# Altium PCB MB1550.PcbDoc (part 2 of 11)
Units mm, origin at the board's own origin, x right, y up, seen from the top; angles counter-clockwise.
Board outline 154.81 x 170.69 mm, 6 copper layers (Top Layer, Signal Layer 1, Signal Layer 2, Signal Layer 3, Signal Layer 4, Bottom Layer), stack 1.49 mm thick; 810 components, 633 nets, 2973 pads, 2150 vias.
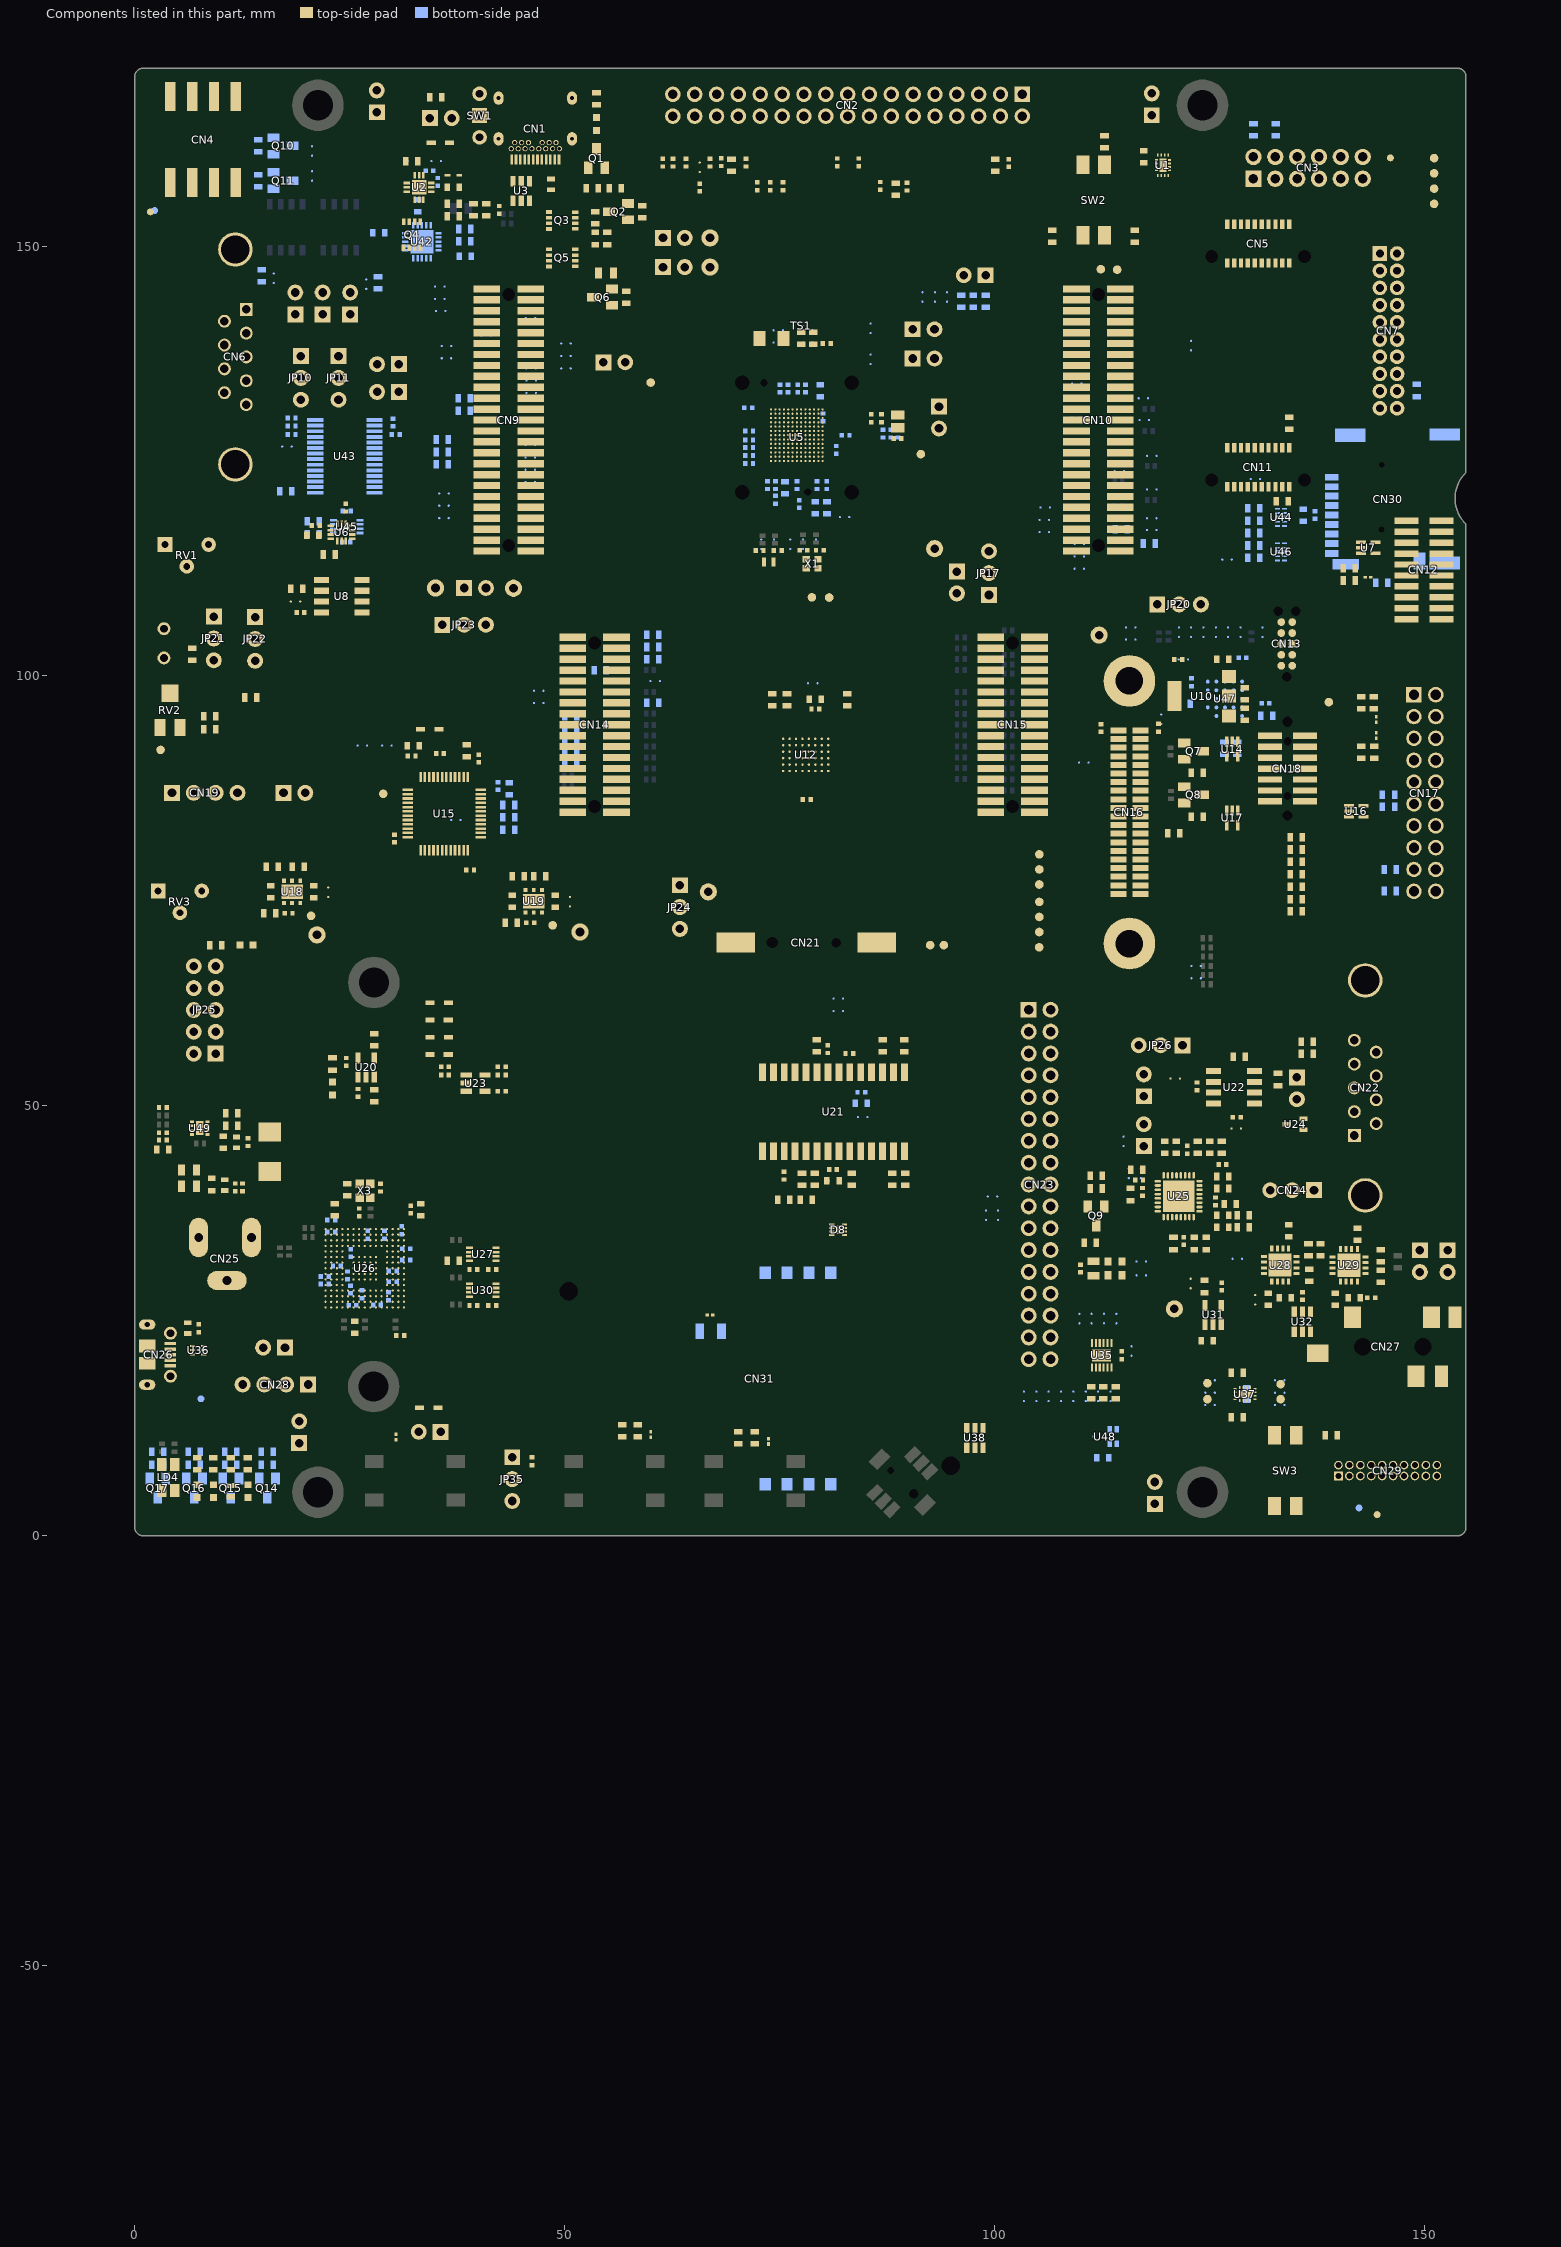
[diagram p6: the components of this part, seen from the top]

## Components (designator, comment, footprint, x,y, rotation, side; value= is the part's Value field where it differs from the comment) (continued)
R251 "Resistor" R0603 11.264,49.162 r180 top value=1K
R252 "Resistor" R0805 6.309,40.655 r180 top value=0R
RV1 "" POT_BOURNS_3386P-1-101TLF 6.055,115.265 r0 top value=10K
RV2 "" POT_BOURNS_3314J-1 4.1,96 r0 top value=10K
RV3 "" POT_BOURNS_3386P 5.254,74.98 r0 top value=50K
SB1 "" SOLDER-BRIDGE_R0603-0R 65.7,159.2 r270 top
SB2 "" SOLDER-BRIDGE_R0603-0R 18.75,108.65 r180 top
SB3 "" SOLDER-BRIDGE_R0603-0R 22.5,74.9 r270 top
SB4 "" SOLDER-BRIDGE_R0603-0R 50.6,73.8 r270 top
SB5 "" SOLDER-BRIDGE_R0603-0R 120.95,53.175 r0 top
SB6 "" SOLDER-BRIDGE_R0603-0R 128.05,47.375 r0 top
SB7 "" SOLDER-BRIDGE_R0603-0R 122.8,29.3 r90 top
SB8 "" SOLDER-BRIDGE_R0603-0R 130.3,27.4 r90 top
SB9 "" SOLDER-BRIDGE_R0603-0R 20.625,161.1 r270 bottom
SB10 "" SOLDER-BRIDGE_R0603-0R 32.225,159.875 r0 bottom
SB11 "" SOLDER-BRIDGE_R0603-0R 35.1,159.875 r180 bottom
SB12 "" SOLDER-BRIDGE_R0603-0R 20.625,158.2 r270 bottom
SB13 "" SOLDER-BRIDGE_R0603-0R 16.175,146.3 r270 bottom
SB14 "" SOLDER-BRIDGE_R0603-0R 26.925,145.525 r90 bottom
SB15 "" SOLDER-BRIDGE_R0603-0R 35.525,145.275 r180 bottom
SB16 "" SOLDER-BRIDGE_R0603-0R 94.475,144.025 r90 bottom
SB17 "" SOLDER-BRIDGE_R0603-0R 93.05,144.025 r90 bottom
SB18 "" SOLDER-BRIDGE_R0603-0R 91.6,144.025 r90 bottom
SB19 "" SOLDER-BRIDGE_R0603-0R 35.525,143.85 r180 bottom
SB20 "" SOLDER-BRIDGE_R0603-0R 35.525,142.45 r0 bottom
SB21 "" SOLDER-BRIDGE_R0603-0R 46.075,141.625 r180 bottom
SB22 "" SOLDER-BRIDGE_R0603-0R 40.9,141.4 r180 bottom
SB23 "" SOLDER-BRIDGE_R0603-0R 85.575,140.375 r90 bottom
SB24 "" SOLDER-BRIDGE_R0603-0R 78.225,140.2 r0 bottom
SB25 "" SOLDER-BRIDGE_R0603-0R 74.9,140.2 r180 bottom
SB26 "" SOLDER-BRIDGE_R0603-0R 46.05,140.075 r180 bottom
SB27 "" SOLDER-BRIDGE_R0603-0R 40.9,139.575 r180 bottom
SB28 "" SOLDER-BRIDGE_R0603-0R 122.85,138.475 r270 bottom
SB29 "" SOLDER-BRIDGE_R0603-0R 78.225,138.775 r0 bottom
SB30 "" SOLDER-BRIDGE_R0603-0R 74.9,138.775 r180 bottom
SB31 "" SOLDER-BRIDGE_R0603-0R 50.1,138.675 r0 bottom
SB32 "" SOLDER-BRIDGE_R0603-0R 46.05,138.65 r0 bottom
SB33 "" SOLDER-BRIDGE_R0603-0R 36.3,138.375 r180 bottom
SB34 "" SOLDER-BRIDGE_R0603-0R 85.575,136.875 r270 bottom
SB35 "" SOLDER-BRIDGE_R0603-0R 40.9,137.4 r180 bottom
SB36 "" SOLDER-BRIDGE_R0603-0R 50.1,137.225 r0 bottom
SB37 "" SOLDER-BRIDGE_R0603-0R 46.05,137.2 r0 bottom
SB38 "" SOLDER-BRIDGE_R0603-0R 36.3,136.95 r180 bottom
SB39 "" SOLDER-BRIDGE_R0603-0R 50.1,135.775 r0 bottom
SB40 "" SOLDER-BRIDGE_R0603-0R 46.05,135.775 r0 bottom
SB41 "" SOLDER-BRIDGE_R0603-0R 46.05,134.35 r0 bottom
SB42 "" SOLDER-BRIDGE_R0603-0R 109.5,134 r0 bottom
SB43 "" SOLDER-BRIDGE_R0603-0R 46.05,132.925 r0 bottom
SB44 "" SOLDER-BRIDGE_R0603-0R 109.5,132.575 r0 bottom
SB45 "" SOLDER-BRIDGE_R0603-0R 117.35,132.3 r180 bottom
SB46 "" SOLDER-BRIDGE_R0603-0R 41.025,132.3 r0 bottom
SB47 "" SOLDER-BRIDGE_R0603-0R 109.5,131.15 r0 bottom
SB48 "" SOLDER-BRIDGE_R0603-0R 114.425,131.05 r0 bottom
SB49 "" SOLDER-BRIDGE_R0603-0R 41.033,130.85 r0 bottom
SB50 "" SOLDER-BRIDGE_R0603-0R 117.35,129.75 r0 bottom
SB51 "" SOLDER-BRIDGE_R0603-0R 109.5,128.725 r0 bottom
SB52 "" SOLDER-BRIDGE_R0603-0R 41.025,128.5 r0 bottom
SB53 "" SOLDER-BRIDGE_R0603-0R 109.5,127.4 r0 bottom
SB54 "" SOLDER-BRIDGE_R0603-0R 114.425,127.175 r180 bottom
SB55 "" SOLDER-BRIDGE_R0603-0R 46.05,126.875 r180 bottom
SB56 "" SOLDER-BRIDGE_R0603-0R 17.65,126.675 r0 bottom
SB57 "" SOLDER-BRIDGE_R0603-0R 118.225,125.6 r0 bottom
SB58 "" SOLDER-BRIDGE_R0603-0R 46.05,125.4 r180 bottom
SB59 "" SOLDER-BRIDGE_R0603-0R 40.917,124.864 r180 bottom
SB60 "" SOLDER-BRIDGE_R0603-0R 46.05,123.975 r180 bottom
SB61 "" SOLDER-BRIDGE_R0603-0R 114.45,123.825 r0 bottom
SB62 "" SOLDER-BRIDGE_R0603-0R 40.917,123.414 r180 bottom
SB63 "" SOLDER-BRIDGE_R0603-0R 109.8,123.4 r0 bottom
SB64 "SB_ON" SOLDER-BRIDGE_R0603-0R 130.375,122.9 r180 bottom
SB65 "" SOLDER-BRIDGE_R0603-0R 46.05,122.55 r180 bottom
SB66 "" SOLDER-BRIDGE_R0603-0R 118.225,121.7 r0 bottom
SB67 "" SOLDER-BRIDGE_R0603-0R 36.012,121.225 r180 bottom
SB68 "" SOLDER-BRIDGE_R0603-0R 46.05,121.1 r180 bottom
SB69 "" SOLDER-BRIDGE_R0603-0R 114.417,120.966 r0 bottom
SB70 "" SOLDER-BRIDGE_R0603-0R 40.9,120.875 r180 bottom
SB71 "" SOLDER-BRIDGE_R0603-0R 36.012,119.8 r180 bottom
SB72 "" SOLDER-BRIDGE_R0603-0R 46.05,119.675 r180 bottom
SB73 "" SOLDER-BRIDGE_R0603-0R 109.8,119.625 r0 bottom
SB74 "" SOLDER-BRIDGE_R0603-0R 105.825,119.6 r0 bottom
SB75 "" SOLDER-BRIDGE_R0603-0R 40.905,118.5 r0 bottom
SB76 "" SOLDER-BRIDGE_R0603-0R 82.6,118.475 r180 bottom
SB77 "" SOLDER-BRIDGE_R0603-0R 118.225,118.35 r0 bottom
SB78 "" SOLDER-BRIDGE_R0603-0R 36.012,118.35 r180 bottom
SB79 "" SOLDER-BRIDGE_R0603-0R 46.05,118.25 r180 bottom
SB80 "" SOLDER-BRIDGE_R0603-0R 109.8,118.2 r0 bottom
SB81 "" SOLDER-BRIDGE_R0603-0R 105.825,118.15 r180 bottom
SB82 "" SOLDER-BRIDGE_R0603-0R 40.905,117.075 r0 bottom
SB83 "" SOLDER-BRIDGE_R0603-0R 118.225,116.975 r0 bottom
SB84 "" SOLDER-BRIDGE_R0603-0R 109.8,116.75 r0 bottom
SB85 "" SOLDER-BRIDGE_R0603-0R 105.825,116.725 r180 bottom
SB86 "" SOLDER-BRIDGE_R0603-0R 74.35,115.275 r90 bottom
SB87 "" SOLDER-BRIDGE_R0603-0R 72.85,115.275 r90 bottom
SB88 "" SOLDER-BRIDGE_R0603-0R 79.225,115.275 r90 bottom
SB89 "" SOLDER-BRIDGE_R0603-0R 77.725,115.275 r90 bottom
SB90 "" SOLDER-BRIDGE_R0603-0R 76.225,115.275 r90 bottom
SB91 "" SOLDER-BRIDGE_R0603-0R 109.8,115.35 r0 bottom
SB92 "" SOLDER-BRIDGE_R0603-0R 109.8,113.9 r0 bottom
SB93 "" SOLDER-BRIDGE_R0603-0R 126.975,113.525 r0 bottom
SB94 "" SOLDER-BRIDGE_R0603-0R 109.8,112.475 r0 bottom
SB95 "" SOLDER-BRIDGE_R0603-0R 131.15,105.15 r270 bottom
SB96 "" SOLDER-BRIDGE_R0603-0R 128.6,105.15 r270 bottom
SB97 "" SOLDER-BRIDGE_R0603-0R 127.15,105.15 r270 bottom
SB98 "" SOLDER-BRIDGE_R0603-0R 125.725,105.15 r270 bottom
SB99 "" SOLDER-BRIDGE_R0603-0R 124.275,105.15 r270 bottom
SB100 "" SOLDER-BRIDGE_R0603-0R 122.85,105.15 r270 bottom
SB101 "" SOLDER-BRIDGE_R0603-0R 121.425,105.15 r270 bottom
SB102 "" SOLDER-BRIDGE_R0603-0R 115.775,105.65 r0 bottom
SB103 "" SOLDER-BRIDGE_R0603-0R 115.775,104.225 r0 bottom
SB104 "" SOLDER-BRIDGE_R0603-0R 121.9,101.925 r0 bottom
SB105 "" SOLDER-BRIDGE_R0603-0R 60.475,99.4 r0 bottom
SB106 "" SOLDER-BRIDGE_R0603-0R 78.9,99.15 r180 bottom
SB107 "" SOLDER-BRIDGE_R0603-0R 47.025,98.275 r180 bottom
SB108 "" SOLDER-BRIDGE_R0603-0R 47.025,96.85 r180 bottom
SB109 "" SOLDER-BRIDGE_R0603-0R 119.384,94.921 r90 bottom
SB110 "" SOLDER-BRIDGE_R0603-0R 29.275,91.9 r0 bottom
SB111 "" SOLDER-BRIDGE_R0603-0R 26.425,91.9 r0 bottom
SB112 "" SOLDER-BRIDGE_R0603-0R 110.425,89.925 r180 bottom
SB113 "" SOLDER-BRIDGE_R0603-0R 37.4,83.25 r180 bottom
SB114 "" SOLDER-BRIDGE_R0603-0R 123.375,66.275 r0 bottom
SB115 "" SOLDER-BRIDGE_R0603-0R 123.375,64.85 r0 bottom
SB116 "" SOLDER-BRIDGE_R0603-0R 81.775,62.475 r0 bottom
SB117 "" SOLDER-BRIDGE_R0603-0R 81.775,61.025 r0 bottom
SB118 "" SOLDER-BRIDGE_R0603-0R 84.7,48.7 r180 bottom
SB119 "" SOLDER-BRIDGE_R0603-0R 115,45.825 r90 bottom
SB120 "" SOLDER-BRIDGE_R0603-0R 117,42.2 r270 bottom
SB121 "" SOLDER-BRIDGE_R0603-0R 115.6,42.2 r270 bottom
SB122 "" SOLDER-BRIDGE_R0603-0R 81.3,41.3 r180 bottom
SB123 "" SOLDER-BRIDGE_R0603-0R 99.7,39.475 r0 bottom
SB124 "" SOLDER-BRIDGE_R0603-0R 100.4,37.35 r270 bottom
SB125 "" SOLDER-BRIDGE_R0603-0R 99,37.35 r270 bottom
SB126 "" SOLDER-BRIDGE_R0603-0R 128.275,32.225 r180 bottom
SB127 "" SOLDER-BRIDGE_R0603-0R 117.1,31.9 r180 bottom
SB128 "" SOLDER-BRIDGE_R0603-0R 117.1,30.3 r180 bottom
SB129 "" SOLDER-BRIDGE_R0603-0R 114.15,25.225 r90 bottom
SB130 "" SOLDER-BRIDGE_R0603-0R 112.725,25.225 r90 bottom
SB131 "" SOLDER-BRIDGE_R0603-0R 111.275,25.225 r90 bottom
SB132 "" SOLDER-BRIDGE_R0603-0R 109.85,25.225 r90 bottom
SB133 "" SOLDER-BRIDGE_R0603-0R 115.925,21.55 r270 bottom
SB134 "" SOLDER-BRIDGE_R0603-0R 133.1,18.1 r0 bottom
SB135 "" SOLDER-BRIDGE_R0603-0R 125.1,18.1 r180 bottom
SB136 "" SOLDER-BRIDGE_R0603-0R 113.475,16.275 r270 bottom
SB137 "" SOLDER-BRIDGE_R0603-0R 112.025,16.275 r270 bottom
SB138 "" SOLDER-BRIDGE_R0603-0R 110.6,16.275 r270 bottom
SB139 "" SOLDER-BRIDGE_R0603-0R 109.15,16.275 r270 bottom
SB140 "" SOLDER-BRIDGE_R0603-0R 107.725,16.275 r270 bottom
SB141 "" SOLDER-BRIDGE_R0603-0R 106.275,16.275 r270 bottom
SB142 "" SOLDER-BRIDGE_R0603-0R 104.85,16.275 r270 bottom
SB143 "" SOLDER-BRIDGE_R0603-0R 103.4,16.275 r270 bottom
SB144 "" SOLDER-BRIDGE_R0603-0R 133.1,16.65 r0 bottom
SB145 "" SOLDER-BRIDGE_R0603-0R 125.1,16.65 r180 bottom
SB146 "" SOLDER-BRIDGE_R0603-0R 133.1,15.225 r0 bottom
SB147 "" SOLDER-BRIDGE_R0603-0R 125.1,15.225 r180 bottom
SW1 "SW_MECA_1K2" SWI_EAO_09-03290-01_EXTENDED_STRAIGHT_BLACK 40.1,165.175 r0 top value="Mechanical Slide Switch 1K2"
SW2 "SWITCH_2WAY" SWI_C&K_SDA02H1SBD_2POS 111.525,155.35 r0 top
SW3 "SWITCH_2WAY" SWI_C&K_SDA02H1SBD_2POS 133.8,7.6 r0 top
TP1 "Test Point" TP_SMD_1MM 151.1,160.225 r270 top
TP2 "Test Point" TP_SMD_1MM 151.1,158.45 r90 top
TP3 "Test Point" TP_SMD_1MM 151.1,156.675 r90 top
TP4 "Test Point" TP_SMD_1MM 151.1,154.9 r90 top
TP5 "" TP_PTH_1MM_2MM 66.9,150.945 r90 top value=VDDIO
TP6 "" TP_PTH_1MM_2MM 66.9,147.55 r180 top value=VDD_USB
TP7 "" TP_SMD_1MM 112.35,147.3 r90 top value=I2C_SDA
TP8 "" TP_SMD_1MM 114.25,147.25 r90 top value=I2C_SCL
TP9 "" TP_SMD_1MM 60,134.125 r0 top value=COMP2_OUT
TP10 "Test Point" TP_SMD_1MM 91.425,125.8 r90 top value=VDDSMPS_CIN
TP11 "" TP_PTH_1MM_2MM 93.025,114.8 r180 top value=VDDA
TP12 "" TP_PTH_1MM_2MM 34.975,110.225 r0 top value=VDD
TP13 "" TP_PTH_1MM_2MM 44.05,110.2 r0 top value=VDD_MCU
TP14 "" TP_SMD_1MM 78.75,109.15 r90 top value=OPAMP2_VINM
TP15 "" TP_SMD_1MM 80.75,109.125 r90 top value=OPAMP1_VINM
TP16 "" TP_PTH_1MM_2MM 112.15,104.75 r270 top value=2V8
TP17 "" TP_SMD_1MM 138.86,96.959 r0 top value=VPP
TP18 "" TP_SMD_1MM 3,91.4 r0 top value=OPAMP1_VOUT
TP19 "" TP_SMD_1MM 28.9,86.3 r90 top value=1mm
TP20 "Test Point" TP_SMD_1MM 105.2,79.25 r180 top
TP21 "Test Point" TP_SMD_1MM 105.2,77.5 r180 top
TP22 "Test Point" TP_SMD_1MM 105.2,75.75 r180 top
TP23 "" TP_PTH_1MM_2MM 66.7,74.9 r90 top value=VBAT
TP24 "Test Point" TP_SMD_1MM 105.2,73.725 r180 top
TP25 "" TP_SMD_1MM 20.5,72.1 r90 top value=1mm
TP26 "Test Point" TP_SMD_1MM 105.2,71.975 r180 top
TP27 "" TP_SMD_1MM 48.6,71 r90 top value=1mm
TP28 "" TP_PTH_1MM_2MM 51.775,70.225 r90 top value=3V3
TP29 "" TP_PTH_1MM_2MM 21.2,69.9 r90 top value=VDD_ADJ
TP30 "Test Point" TP_SMD_1MM 105.2,70.225 r180 top
TP31 "" TP_SMD_1MM 92.5,68.7 r180 top value=AUX1UC
TP32 "" TP_SMD_1MM 94.1,68.7 r180 top value=AUX2UC
TP33 "Test Point" TP_SMD_1MM 105.175,68.45 r180 top
TP34 "" TP_PTH_1MM_2MM 120.9,26.4 r90 top value=1V8
TP35 "" TP_SMD_1MM 124.75,17.75 r0 top value=ADF1_SDIN0
TP36 "" TP_SMD_1MM 133.25,17.65 r0 top value=ADF1_CCK0
TP37 "" TP_SMD_1MM 124.75,15.9 r0 top value=MDF1_CCK0
TP38 "" TP_SMD_1MM 133.25,15.9 r180 top value=MDF1_SDIN0
TS1 "" TSB_TOUCH-SENSING-BUTTON_TS-PAD-10_SHIELD-14 77.5,148 r0 top value=TS_PAD
U1 "STG3692QTR" ICC_UFQFN16-EPAD_2P6X1P8_P040 119.575,159.4 r270 top
U2 "" ICC_QFN12L-EPAD_3X3_P050 33.075,156.825 r270 top value=TCPP01-M12
U3 "USBLC6-2SC6" ESD_SOT23-6L 44.95,156.4 r0 top
U4 "" ESD_QFN1610_2N_1K_2A 48.4,157.175 r270 top value=ESDA25P35-1U1M
U5 "STM32U575AII6QU" ICC_UFBGA169_7X7_P050_PAD025-PM030-SM035_SOCKET_IRONWOOD_CS1627113MF_NM 77,128 r90 top value=STM32U575AII6Q
U6 "LSM6DSO" ICC_LGA14_3X2P5_P050 24.05,116.7 r180 top
U7 "" ESD_SOT323-5L 143.45,114.9 r270 top value=ESDALC6V1W5
U8 "" ICC_SO8_5X4_P127 24.075,109.275 r90 top value=M24128-DFMN6TP
U9 "" ESD_ST0201 143.425,111.475 r180 top value=ESDALC6V1-1U2
U10 "" REG_SOT223-TAB 124.075,97.65 r90 top value=LD1117STR
U11 "" ESD_ST0201 144.375,94.95 r270 top value=ESDALC6V1-1U2
U12 "" ICC_MINI-BGA48_9X11_P075 78.025,90.821 r90 top value=IS61WV102416BLL-10MLI
U13 "" ESD_ST0201 144.375,93.075 r90 top value=ESDALC6V1-1U2
U14 "ESDALC6V1W5" ESD_SOT323-5L 127.625,91.5 r180 top
U15 "" ICC_LQFP48_7X7_P050 35.998,84 r180 top value=STM32L152CCT6
U16 "" ESD_SOT323-5L 142.05,84.275 r270 top value=ESDALC6V1W5
U17 "ESDALC6V1W5" ESD_SOT323-5L 127.625,83.5 r180 top
U18 "" ICC_DFN6-EPAD_3X3_P095 18.3,74.9 r0 top value=ST1L05BPUR
U19 "" ICC_DFN6-EPAD_3X3_P095 46.4,73.8 r0 top value=ST1L05BPUR
U20 "TPS2051C" MOS_SOT23-5L 26.9,54.475 r0 top
U21 "" ICC_SO28_18P10X7P60_P127 81.25,49.341 r180 top value=ST8024LACDR
U22 "" ICC_SO8_5X4_P127 127.85,52.175 r270 top value=MCP2562FDT-H/SN
U23 "LD3985M33R" REG_SOT23-5L 39.65,52.65 r270 top
U24 "ESD-TRANSIL-DUAL-BIDIR" DIO_SOT323 134.95,47.875 r90 top value=ESDCAN05-2BWY
U25 "" ICC_QFN32-EPAD_5X5_P050 121.4,39.5 r0 top value=CS42L51-CNZ
U26 "" ICC_UFBGA201_176+25_10X10_P065 26.75,31.125 r270 top value=ST-LINKV3E_SWD
U27 "SN74LVC2T45DCUT" ICC_VSSOP8_DCU_R-PDSO-G8_2X2P30_P050 40.475,32.75 r90 top
U28 "" ICC_QFN16-EPAD_4X4_P065 133.2,31.5 r0 top value=STPMS2L-PUR
U29 "" ICC_QFN16-EPAD_4X4_P065 141.2,31.48 r0 top value=STPMS2L-PUR
U30 "SN74LVC2T45DCUT" ICC_VSSOP8_DCU_R-PDSO-G8_2X2P30_P050 40.475,28.575 r90 top
U31 "" REG_SOT23-5L 125.4,25.7 r0 top value=LD3985M18R
U32 "" ESD_SOT23-6L 135.8,24.9 r0 top value=ESDA6V1BC6
U33 "ESD-TRANSIL" ESD_ST0201 66.9,25.7 r0 top value=ESDALC6V1-1U2
U34 "" ESD_QFN1610_2N_1K_2A 6.175,24.15 r90 top value=ESDA7P120-1U1M
U35 "SX8651" ICC_DFN12-EPAD_3X3_P045 112.45,21 r180 top
U36 "" ESD_QFN-6L_1P7X1P5_P050 7.375,21.6 r90 top value=ECMF02-2AMX6
U37 "STG3692QTR" ICC_UFQFN16-EPAD_2P6X1P8_P040 129.1,16.5 r180 top
U38 "" ESD_SOT23-6L 97.7,11.4 r180 top value=ESDA6V1-5SC6
U39 "" ESD_ST0201 60,11.8 r90 top value=ESDALC6V1-1U2
U40 "" ESD_ST0201 30.4,11.5 r90 top value=ESDALC6V1-1U2
U41 "" ESD_ST0201 73.7,11 r90 top value=ESDALC6V1-1U2
U42 "TCPP03-M20" ICC_QFN20-EPAD_4X4_P050 33.4,150.5 r0 bottom
U43 "" ICC_SSOP28_10P2X5P3_P065 24.426,125.536 r270 bottom value=ST3241EBPR
U44 "" ESD_UQFN-10L_2P5X1_P050 133.325,118.45 r90 bottom value=HSP051-4M10
U45 "" ICC_VSSOP8_DCU_R-PDSO-G8_2X2P30_P050 24.65,117.375 r90 bottom value=SN74LVC2T45DCUT
U46 "" ESD_UQFN-10L_2P5X1_P050 133.325,114.425 r90 bottom value=HSP051-4M10
U47 "MX25LM51245GXDI00" ICC_BGA24_5X5-BALL-ARRAY_6X8_P1 126.784,97.346 r0 bottom
U48 "MP23DB01MMTR" MIC_STM_MP23DB01MMTR 112.825,11.55 r90 bottom value=MP23DB01HPTR
U49 "TPS259533DSG" ICC_WSON8-EPAD_2X2_P050 7.571,47.427 r0 top
U50 "ESD-TRANSIL" ESD_QFN1610_2N_1K_2A 10.456,40.784 r270 top value=ESDA13P70-1U1M
U51 "ESD-TRANSIL" ESD_QFN2_1P6X1_P125 11.816,45.752 r270 top value=ESDA7P60-1U1M
X1 "XTAL_4_PINS" CRY_NX2016SA_4P 78.775,113.075 r0 top value="NX2016SA 16MHz"
X2 "XTAL_2_PINS" CRY_NX1610SE_2P 73.725,113.25 r180 top value="NX1610SE 32.768kHz"
X3 "" OSC_NDK_NZ2520SB_4P 26.775,40.125 r270 top value="NZ2520SH 25MHz"

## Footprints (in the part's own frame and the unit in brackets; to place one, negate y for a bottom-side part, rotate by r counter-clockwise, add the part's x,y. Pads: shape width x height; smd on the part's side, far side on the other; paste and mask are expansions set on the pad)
BAT_HARWIN_S8411-45R_SMD_2P [mm] "CR1220 HOLDER"
  rect 4.5x2.3 smd mask+0.05: 1(8.2,0) 2(-8.2,0)
  round 0 hole 1.1 unplated mask+0.05: NPTH1(-3.5,0)
  round 0 hole 1.3 unplated mask+0.05: NPTH2(3.95,0)
  silkscreen extent -9.03,-7.5 9.62,7.5, body extent -8.93,-7.5 9.88,7.5, height 4.31
C0402 [mm]
  rect 0.51x0.56 smd mask+0.05: 1(-0.45,0) 2(0.45,0)
  silkscreen extent 0,-0.3 0,0.3, body extent -0.5,-0.3 0.5,0.3, height 0.4
C0603 [mm]
  rect 0.64x0.89 smd mask+0.05: 1(-0.7,0) 2(0.7,0)
  silkscreen extent -1.05,-0.55 1.02,0.55, body extent -0.9,-0.5 0.9,0.5, height 1.4
C0805 [mm]
  rect 0.9x1.4 smd mask+0.05: 1(-0.85,0) 2(0.85,0)
  silkscreen extent -1.3,-0.77 1.3,0.77, body extent -1.1,-0.7 1.1,0.7, height 1.35
C1206_H0P85 [mm]
  rect 1.4x1.78 smd mask+0.05: 1(-1.4,0) 2(1.4,0)
  silkscreen extent -2.12,-0.97 2.15,0.97, body extent -1.6,-0.8 1.6,0.8, height 0.95
CON_CARD-SOCKET_GUANG-LIAN-WEI_2480-208-503-100-RC [mm]
  rect 1.5x1.3 smd mask+0.05: C1(-12.3,-3.81) C2(-12.3,-1.27) C3(-12.3,1.27) C4(-12.3,3.81) C5(12.3,-3.81) C6(12.3,-1.27) C7(12.3,1.27) C8(12.3,3.81)
  round 0 hole 2.15 unplated mask+0.05: NPTH1(-10.16,26.67) NPTH2(10.16,-17.78)
  rect 1.75x1 smd mask+0.05: S1(-5.5,8.89) S2(-5.5,11.43)
  silkscreen extent -16.96,-24.89 14.14,31.11, body extent -28.25,-24.89 14.14,31.11, height 3.86
CON_CVILUX_CH87-20-2-V-1-00 [mm]
  rect 1.8x1.8 hole 1.2 mask+0.05: 1(-11.43,-1.27)
  round 1.8 hole 1.2 mask+0.05: 2(-11.43,1.27) 3(-8.89,-1.27) 4(-8.89,1.27) 5(-6.35,-1.27) 6(-6.35,1.27) 7(-3.81,-1.27) 8(-3.81,1.27) 9(-1.27,-1.27) 10(-1.27,1.27) 11(1.27,-1.27) 12(1.27,1.27) 13(3.81,-1.27) 14(3.81,1.27) 15(6.35,-1.27) 16(6.35,1.27) 17(8.89,-1.27) 18(8.89,1.27) 19(11.43,-1.27) 20(11.43,1.27)
  silkscreen extent -16.51,-4.55 16.51,4.55, body extent -16.51,-4.57 16.51,4.57, height 9.86
CON_DB9-MALE_TYCO_2301843-2 [mm] "MCD-00127"
  rect 1.5x1.5 / inner round 1.5 / far side rect 1.5x1.5 hole 1 mask+0.05: 1(-5.54,8.77)
  round 1.5 hole 1 mask+0.05: 2(-2.77,8.77) 3(0,8.77) 4(2.77,8.77) 5(5.54,8.77) 6(-4.155,6.23) 7(-1.385,6.23) 8(1.385,6.23) 9(4.155,6.23)
  round 4 hole 3.3 mask+0.05: MT1(-12.5,7.5) MT2(12.5,7.5)
  silkscreen extent -15.5,-10.3 15.5,10.6, body extent -15.5,-10.3 15.5,10.6, height 13.8
CON_DC-POWER-SOCKET_CLIFF_FC68149_DC10B [mm]
  oval 2.2x4.6 hole 1 slot 3.5 at 90 deg mask+0.05: 1(-13.55,0) 3(-7.4,0)
  oval 4.6x2.2 hole 1 slot 3.5 at 0 deg mask+0.05: 2(-10.7,5)
  silkscreen extent -14.2,-4.6 0,4.6, body extent -14.3,-4.6 0.2,5.27, height 11
CON_FCI_20021311-XXX20XXLF [mm]
  rect 1x1 / inner round 1 / far side rect 1x1 hole 0.7 mask+0.05: 1(5.715,0.635)
  round 1 hole 0.7 mask+0.05: 2(5.715,-0.635) 3(4.445,0.635) 4(4.445,-0.635) 5(3.175,0.635) 6(3.175,-0.635) 7(1.905,0.635) 8(1.905,-0.635) 9(0.635,0.635) 10(0.635,-0.635) 11(-0.635,0.635) 12(-0.635,-0.635) 13(-1.905,0.635) 14(-1.905,-0.635) 15(-3.175,0.635) 16(-3.175,-0.635) 17(-4.445,0.635) 18(-4.445,-0.635) 19(-5.715,0.635) 20(-5.715,-0.635)
  silkscreen extent -6.58,-1.5 6.58,1.5, body extent -6.58,-1.5 6.58,1.5, height 4.4
CON_MICROSD_YAMAICHI_PJS008-2003-1 [mm] "WITH POSITIONNING PINS"
  rect 1.6x0.8 smd paste+0 mask+0.05: 1(-15.6,-2.525) 2(-15.6,-1.425) 3(-15.6,-0.325) 4(-15.6,0.775) 5(-15.6,1.875) 6(-15.6,2.975) 7(-15.6,4.075) 8(-15.6,5.175) 9(-15.6,6.325)
  rect 1.4x1.95 smd paste+0 mask+0.05: 10(-5.4,7.225)
  rect 3.5x1.5 smd paste+0 mask+0.05: 11(-2.45,7.45)
  rect 3.5x1.4 smd paste+0 mask+0.05: 12(-2.45,-7.5)
  rect 3.5x1.6 smd paste+0 mask+0.05: 13(-13.45,-7.4)
  rect 3.1x1.2 smd paste+0 mask+0.05: 14(-13.95,7.6)
  round 0 hole 0.65 unplated mask+0.05: NPTH1(-9.8,-4)
  round 0 hole 0.7 unplated mask+0.05: NPTH2(-9.8,3.55)
  silkscreen extent -15.32,-7.25 5.65,7.25, body extent -15.25,-7.25 -0.45,7.42, height 2
CON_PHONE-JACK-3P5_HY_PJ3028B [mm]
  rect 1.5x2.5 smd mask+0.05: 2(1.25,-3.45) 7(2.85,3.45)
  rect 2x2.5 smd mask+0.05: 3(4,-3.45) 4(5.8,3.45) 6(13.2,-3.45)
  rect 2.5x2 smd mask+0.05: 5(17.25,0.75)
  round 0.5 hole 2 unplated mask+0.1: MT1(5,0) MT2(12,0)
  Multi-Layer keep-out circle w0.01: c5,0 r1.25
  Multi-Layer keep-out circle w0.01: c12,0 r1.25
  silkscreen extent -0.9,-3.7 16,3, body extent -0.9,-3 16,3, height 5
CON_SAMTEC_CLM-120-02-L-D_Reverse-to-Camera [mm] "not in line with Samtec spec"
  rect 1.85x0.7 smd mask+0.05: 1(-1.275,9.5) 2(1.275,9.5) 3(-1.275,8.5) 4(1.275,8.5) 5(-1.275,7.5) 6(1.275,7.5) 7(-1.275,6.5) 8(1.275,6.5) 9(-1.275,5.5) 10(1.275,5.5) 11(-1.275,4.5) 12(1.275,4.5) 13(-1.275,3.5) 14(1.275,3.5) 15(-1.275,2.5) 16(1.275,2.5) 17(-1.275,1.5) 18(1.275,1.5) 19(-1.275,0.5) 20(1.275,0.5) 21(-1.275,-0.5) 22(1.275,-0.5) 23(-1.275,-1.5) 24(1.275,-1.5) 25(-1.275,-2.5) 26(1.275,-2.5) 27(-1.275,-3.5) 28(1.275,-3.5) 29(-1.275,-4.5) 30(1.275,-4.5) 31(-1.275,-5.5) 32(1.275,-5.5) 33(-1.275,-6.5) 34(1.275,-6.5) 35(-1.275,-7.5) 36(1.275,-7.5) 37(-1.275,-8.5) 38(1.275,-8.5) 39(-1.275,-9.5) 40(1.275,-9.5)
  round 6 hole 3.2 mask+0.1: 41(0,15.27) 42(0,-15.27)
  silkscreen extent -16.5,-19 6,21, body extent -16.5,-19 6,21, height 5.69
CON_SAMTEC_ERF8-010-050-S-DV-TR [mm]
  rect 0.5x1.1 smd mask+0.05: 1(3.6,2.25) 2(3.6,-2.25) 3(2.8,2.25) 4(2.8,-2.25) 5(2,2.25) 6(2,-2.25) 7(1.2,2.25) 8(1.2,-2.25) 9(0.4,2.25) 10(0.4,-2.25) 11(-0.4,2.25) 12(-0.4,-2.25) 13(-1.2,2.25) 14(-1.2,-2.25) 15(-2,2.25) 16(-2,-2.25) 17(-2.8,2.25) 18(-2.8,-2.25) 19(-3.6,2.25) 20(-3.6,-2.25)
  round 0 hole 1.5 unplated mask+0.1: NPTH1(5.4,-1.5) NPTH2(-5.4,-1.5)
  Multi-Layer keep-out circle w0.01: c-5.4,-1.5 r0.951
  Multi-Layer keep-out circle w0.01: c5.4,-1.5 r0.951
  silkscreen extent -7,-2.8 7,2.8, body extent -7,-2.8 7,2.8, height 5.3
CON_SAMTEC_FTR-117-03-L-D-LC [mm] "Header 17x2, 1.27mm, VR, CMS, Height 7.24mm, locking-clip"
  rect 0.85x3.1 smd mask+0.05: 1(-10.16,-2.55) 2(-10.16,2.55) 3(-8.89,-2.55) 4(-8.89,2.55) 5(-7.62,-2.55) 6(-7.62,2.55) 7(-6.35,-2.55) 8(-6.35,2.55) 9(-5.08,-2.55) 10(-5.08,2.55) 11(-3.81,-2.55) 12(-3.81,2.55) 13(-2.54,-2.55) 14(-2.54,2.55) 15(-1.27,-2.55) 16(-1.27,2.55) 17(0,-2.55) 18(0,2.55) 19(1.27,-2.55) 20(1.27,2.55) 21(2.54,-2.55) 22(2.54,2.55) 23(3.81,-2.55) 24(3.81,2.55) 25(5.08,-2.55) 26(5.08,2.55) 27(6.35,-2.55) 28(6.35,2.55) 29(7.62,-2.55) 30(7.62,2.55) 31(8.89,-2.55) 32(8.89,2.55) 33(10.16,-2.55) 34(10.16,2.55)
  round 0 hole 1.5 unplated mask+0.05: NPTH1(-9.525,0) NPTH2(9.525,0)
  silkscreen extent -10.79,-2.05 10.79,2.05, body extent -10.79,-3.76 10.8,3.76, height 6.99
CON_SAMTEC_FTR-125-03-L-D-LC [mm] "MCD-02111"
  rect 0.85x3.1 smd mask+0.05: 1(-15.24,-2.55) 2(-15.24,2.55) 3(-13.97,-2.55) 4(-13.97,2.55) 5(-12.7,-2.55) 6(-12.7,2.55) 7(-11.43,-2.55) 8(-11.43,2.55) 9(-10.16,-2.55) 10(-10.16,2.55) 11(-8.89,-2.55) 12(-8.89,2.55) 13(-7.62,-2.55) 14(-7.62,2.55) 15(-6.35,-2.55) 16(-6.35,2.55) 17(-5.08,-2.55) 18(-5.08,2.55) 19(-3.81,-2.55) 20(-3.81,2.55) 21(-2.54,-2.55) 22(-2.54,2.55) 23(-1.27,-2.55) 24(-1.27,2.55) 25(0,-2.55) 26(0,2.55) 27(1.27,-2.55) 28(1.27,2.55) 29(2.54,-2.55) 30(2.54,2.55) 31(3.81,-2.55) 32(3.81,2.55) 33(5.08,-2.55) 34(5.08,2.55) 35(6.35,-2.55) 36(6.35,2.55) 37(7.62,-2.55) 38(7.62,2.55) 39(8.89,-2.55) 40(8.89,2.55) 41(10.16,-2.55) 42(10.16,2.55) 43(11.43,-2.55) 44(11.43,2.55) 45(12.7,-2.55) 46(12.7,2.55) 47(13.97,-2.55) 48(13.97,2.55) 49(15.24,-2.55) 50(15.24,2.55)
  round 0 hole 1.5 unplated mask+0.05: NPTH1(-14.605,0) NPTH2(14.605,0)
  silkscreen extent -15.88,-2.05 15.88,2.06, body extent -15.88,-3.76 15.88,3.76, height 6.99
CON_SAMTEC_FTSH-110-01-L-DV [mm]
  rect 0.74x2.79 smd mask+0.05: 1(-5.715,-2.035) 2(-5.715,2.035) 3(-4.445,-2.035) 4(-4.445,2.035) 5(-3.175,-2.035) 6(-3.175,2.035) 7(-1.905,-2.035) 8(-1.905,2.035) 9(-0.635,-2.035) 10(-0.635,2.035) 11(0.635,-2.035) 12(0.635,2.035) 13(1.905,-2.035) 14(1.905,2.035) 15(3.175,-2.035) 16(3.175,2.035) 17(4.445,-2.035) 18(4.445,2.035) 19(5.715,-2.035) 20(5.715,2.035)
  silkscreen extent -6.35,-1.71 6.35,1.71, body extent -6.35,-2.92 6.35,2.92, height 5.97
CON_SAMTEC_SQT-110-01-F-D-RA__STMOD+ [mm] "SQT-110-01-F-D-RA (connecteur SAMTEC pour interface STMod+ femelle coté Host) Pinning adapté non conforme SAMTEC."
  rect 1.7x1.7 hole 0.9 mask+0.05: 1(9,1)
  round 1.7 hole 0.9 mask+0.05: 2(7,1) 3(5,1) 4(3,1) 5(1,1) 6(-1,1) 7(-3,1) 8(-5,1) 9(-7,1) 10(-9,1) 11(9,-1) 12(7,-1) 13(5,-1) 14(3,-1) 15(1,-1) 16(-1,-1) 17(-3,-1) 18(-5,-1) 19(-7,-1) 20(-9,-1)
  silkscreen extent -10.15,-8.62 10.15,0.07, body extent -10.15,-8.65 10.15,1.22, height 4
CON_SAMTEC_SSM-104-L-DH [mm]
  rect 1.2x3.4 smd mask+0.05: 1(3.81,-5) 2(3.81,5) 3(1.27,-5) 4(1.27,5) 5(-1.27,-5) 6(-1.27,5) 7(-3.81,-5) 8(-3.81,5)
  silkscreen extent -5.08,-4.06 5.08,4.06, body extent -5.08,-5.46 5.1,5.46, height 5.92
CON_SAMTEC_SSW-106-02-F-D-RA__PMOD [mm] "SSW-106-02-F-D-RA (connecteur SAMTEC pour interface PMOD femelle coté Host) Pinning adapté non conforme SAMTEC."
  rect 1.9x1.9 hole 1.1 mask+0.05: 1(6.35,1.27)
  round 1.9 hole 1.1 mask+0.05: 2(3.81,1.27) 3(1.27,1.27) 4(-1.27,1.27) 5(-3.81,1.27) 6(-6.35,1.27) 7(6.35,-1.27) 8(3.81,-1.27) 9(1.27,-1.27) 10(-1.27,-1.27) 11(-3.81,-1.27) 12(-6.35,-1.27)
  silkscreen extent -7.88,-11.3 7.88,0.23, body extent -7.87,-11.31 7.87,1.47, height 5.21
CON_SAMTEC_SSW-117-21-X-D_INV [mm] "NUCLEO144_ARDUINO CONNECTOR"
  rect 1.85x1.85 / inner round 1.85 / far side rect 1.85x1.85 hole 1.1 mask+0.05: 1(20.32,1.27)
  round 1.85 hole 1.1 mask+0.05: 2(20.32,-1.27) 3(17.78,1.27) 4(17.78,-1.27) 5(15.24,1.27) 6(15.24,-1.27) 7(12.7,1.27) 8(12.7,-1.27) 9(10.16,1.27) 10(10.16,-1.27) 11(7.62,1.27) 12(7.62,-1.27) 13(5.08,1.27) 14(5.08,-1.27) 15(2.54,1.27) 16(2.54,-1.27) 17(0,1.27) 18(0,-1.27) 19(-2.54,1.27) 20(-2.54,-1.27) 21(-5.08,1.27) 22(-5.08,-1.27) 23(-7.62,1.27) 24(-7.62,-1.27) 25(-10.16,1.27) 26(-10.16,-1.27) 27(-12.7,1.27) 28(-12.7,-1.27) 29(-15.24,1.27) 30(-15.24,-1.27) 31(-17.78,1.27) 32(-17.78,-1.27) 33(-20.32,1.27) 34(-20.32,-1.27)
  silkscreen extent -21.85,-2.47 21.85,2.47, body extent -21.85,-2.48 21.85,2.48, height 8.51
CON_SAMTEC_TST-117-01-T-D [mm]
  rect 1.8x1.8 hole 1.1 mask+0.05: 1(-20.32,-1.27)
  round 1.8 hole 1.1 mask+0.05: 2(-20.32,1.27) 3(-17.78,-1.27) 4(-17.78,1.27) 5(-15.24,-1.27) 6(-15.24,1.27) 7(-12.7,-1.27) 8(-12.7,1.27) 9(-10.16,-1.27) 10(-10.16,1.27) 11(-7.62,-1.27) 12(-7.62,1.27) 13(-5.08,-1.27) 14(-5.08,1.27) 15(-2.54,-1.27) 16(-2.54,1.27) 17(0,-1.27) 18(0,1.27) 19(2.54,-1.27) 20(2.54,1.27) 21(5.08,-1.27) 22(5.08,1.27) 23(7.62,-1.27) 24(7.62,1.27) 25(10.16,-1.27) 26(10.16,1.27) 27(12.7,-1.27) 28(12.7,1.27) 29(15.24,-1.27) 30(15.24,1.27) 31(17.78,-1.27) 32(17.78,1.27) 33(20.32,-1.27) 34(20.32,1.27)
  silkscreen extent -25.4,-4.83 25.4,4.83, body extent -25.4,-4.83 25.4,4.83, height 9.27
CON_SAMTEC_TSW-102-07-G-S [mm]
  rect 1.85x1.85 / inner round 1.85 / far side rect 1.85x1.85 hole 1 mask+0.05: 1(-1.27,0)
  round 1.85 hole 1 mask+0.05: 2(1.27,0)
  silkscreen extent -2.58,-1.3 2.58,1.3, body extent -2.67,-1.3 2.58,1.3, height 8.38
CON_SAMTEC_TSW-103-07-F-S [mm]
  rect 1.85x1.85 / inner round 1.85 / far side rect 1.85x1.85 hole 1 mask+0.05: 1(-2.54,0)
  round 1.85 hole 1 mask+0.05: 2(0,0) 3(2.54,0)
  silkscreen extent -3.85,-1.3 3.85,1.3, body extent -3.94,-1.37 3.91,1.37, height 8.38
CON_SAMTEC_TSW-104-07-G-S [mm]
  rect 1.85x1.85 / inner round 1.85 / far side rect 1.85x1.85 hole 1 mask+0.05: 1(-3.81,0)
  round 1.85 hole 1 mask+0.05: 2(-1.27,0) 3(1.27,0) 4(3.81,0)
  silkscreen extent -5.12,-1.3 5.12,1.3, body extent -5.21,-1.37 5.18,1.37, height 8.38
CON_SAMTEC_TSW-105-07-X-D [mm]
  rect 1.85x1.85 / inner round 1.85 / far side rect 1.85x1.85 hole 1 mask+0.05: 1(-5.08,-1.27)
  round 1.85 hole 1 mask+0.05: 2(-5.08,1.27) 3(-2.54,-1.27) 4(-2.54,1.27) 5(0,-1.27) 6(0,1.27) 7(2.54,-1.27) 8(2.54,1.27) 9(5.08,-1.27) 10(5.08,1.27)
  silkscreen extent -6.35,-2.54 6.35,2.54, body extent -6.35,-2.54 6.35,2.55, height 8.38
CON_STDC14_Receiver_MEDIUM_WITH_MIPI10_3D [mm] "compatible with FTSH-105-01-L-DV,-K and FTSH-107-01-L-DV,-K,-A,-P,-ES"
  round 0 hole 1.19 unplated mask+0.05: 0(-5.445,0) 0(5.445,0)
  round 0 hole 0.97 unplated mask+0.05: 0(-3.175,0) 0(3.175,0)
  rect 0.74x2.79 smd mask+0.05: 1(-3.81,-2.032) 2(-3.81,2.032) 3(-2.54,-2.032) 4(-2.54,2.032) 5(-1.27,-2.032) 6(-1.27,2.032) 7(0,-2.032) 8(0,2.032) 9(1.27,-2.032) 10(1.27,2.032) 11(2.54,-2.032) 12(2.54,2.032) 13(3.81,-2.032) 14(3.81,2.032)
  silkscreen extent -6.3,-4.38 6.3,3.6, body extent -6.3,-2.92 6.3,2.92, height 6.6
CON_TAG-C_TC2050-IDC-NL [mm]
  round 0.9 smd paste+0 mask+0.05: 1(-2.54,-0.635) 2(-1.27,-0.635) 3(0,-0.635) 4(1.27,-0.635) 5(2.54,-0.635) 6(2.54,0.635) 7(1.27,0.635) 8(0,0.635) 9(-1.27,0.635) 10(-2.54,0.635)
  round 0 hole 1.1 unplated mask+0.05: 11(-3.81,0) 12(3.81,-1.015) 13(3.81,1.015)
  Multi-Layer keep-out circle w0.01: c-3.81,0 r0.75
  Multi-Layer keep-out circle w0.01: c3.81,1.015 r0.75
  Multi-Layer keep-out circle w0.01: c3.81,-1.015 r0.75
  silkscreen extent -6.22,-3.4 6.22,3.33, body extent -6.28,-3.46 6.28,3.39, height 13
CON_USB-TYPEC_COXOC_317JD24BZTF3K3C3 [mm]
  rect 0.3x1.2 smd mask+0.05: A1(-2.75,10.58) A2(-2.25,10.58) A3(-1.75,10.58) A4(-1.25,10.58) A5(-0.75,10.58) A6(-0.25,10.58) A7(0.25,10.58) A8(0.75,10.58) A9(1.25,10.58) A10(1.75,10.58) A11(2.25,10.58) A12(2.75,10.58)
  round 0.6 hole 0.4 mask+0.05: B1(2,9.33) B1(2.8,9.33) B2(2.4,8.62) B3(1.6,8.62) B4(1.2,9.33) B5(0.8,8.62) B6(0.4,9.33) B7(-0.4,9.33) B8(-0.8,8.62) B9(-1.2,9.33) B10(-1.6,8.62) B11(-2.4,8.62) B12(-2.8,9.33) B12(-2,9.33)
  oval 1.15x1.55 hole 0.45 slot 0.85 at 90 deg mask+0.05: SH1(-4.27,8.18) SH2(-4.27,3.45) SH3(4.27,8.18) SH4(4.27,3.45)
  silkscreen extent -4.38,-0.95 4.38,10.38, body extent -4.38,-0.95 4.38,10.84, height 3.03
CON_USBMICROB_MOLEX_105017-0001_H2P90 [mm]
  rect 0.4x1.35 smd mask+0.05: 1(-1.3,4.15) 2(-0.65,4.15) 3(0,4.15) 4(0.65,4.15) 5(1.3,4.15)
  round 1.5 hole 0.9 mask+0.05: 6(-2.5,4.15) 7(2.5,4.15)
  oval 1.2x1.9 hole 0.6 slot 1.3 at 90 deg mask+0.05: 8(3.5,1.45) 9(-3.5,1.45)
  rect 1.5x1.9 smd mask+0.05: 10(-1,1.45) 11(1,1.45)
  Top Layer region: 2.3,2.4 3.5,2.4 3.5,0.5 2.3,0.5 2.3,2.4
  Top Layer region: -3.5,2.4 -2.3,2.4 -2.3,0.5 -3.5,0.5 -3.5,2.4
  silkscreen extent -4,-0.7 4,4.6, body extent -4.1,-1.15 4.1,4.66, height 2.9
CPOL_TAJ-C_2312_H2P6 [mm]
  rect 2.2x2.6 smd mask+0.05: 1(-2.3,0) 2(2.3,0)
  silkscreen extent -3.6,-1.85 3.1,1.85, body extent -3.1,-1.7 3.1,1.7, height 2.8
CRY_NX1610SE_2P [mm] "MCD-02291"
  rect 0.5x1 smd mask+0.05: 1(-0.55,0) 2(0.55,0)
  silkscreen extent -0.13,-0.5 0.13,0.5, body extent -0.8,-0.5 0.8,0.5, height 0.45
CRY_NX2016SA_4P [mm]
  rect 0.85x0.75 smd mask+0.05: 1(-0.675,-0.525) 2(0.675,-0.525) 3(0.675,0.525) 4(-0.675,0.525)
  silkscreen extent -1.22,-1.02 1.05,0.85, body extent -1.05,-0.85 1.05,0.85, height 0.7
DIO_SOD323 [mm]
  rect 1.06x0.54 smd mask+0.05: 1(-1.07,0) 2(1.07,0)
  silkscreen extent -0.9,-0.72 0.9,0.72, body extent -1.3,-0.78 1.3,0.78, height 1.17
DIO_SOD523_1A_2K [mm] "MCD-01677"
  rect 0.65x0.3 smd mask+0.05: 1(-0.675,0) 2(0.675,0)
  silkscreen extent -0.65,-0.45 1.05,0.55, body extent -0.85,-0.45 0.85,0.45, height 0.71
DIO_SOT323 [mm]
  rect 0.5x0.95 smd mask+0.05: 1(-0.65,-0.975) 2(0.65,-0.975) 3(0,0.975)
  silkscreen extent -1.15,-0.67 1.15,0.67, body extent -1.15,-1.12 1.15,1.12, height 1.1
ESD_QFN2_1P6X1_P125 [mm]
  rect 0.55x0.8 smd mask+0.05: 1(-0.625,0) 2(0.625,0)
  silkscreen extent -1,-0.55 0.85,0.55, body extent -0.85,-0.55 0.85,0.55, height 0.61
ESD_QFN1610_2N_1K_2A [mm] "DFN, 2-Leads, Body 1.60x1.00mm"
  rect 0.55x0.9 smd mask+0.05: 1(-0.625,0) 2(0.625,0)
  silkscreen extent -1.02,-0.58 0.85,0.58, body extent -0.85,-0.55 0.85,0.55, height 0.6
ESD_QFN-6L_1P7X1P5_P050 [mm]
  rect 0.25x0.6 smd mask+0.05: 1(-0.5,-0.65) 2(0,-0.65) 3(0.5,-0.65) 4(0.5,0.65) 5(0,0.65) 6(-0.5,0.65)
  silkscreen extent -0.9,-0.8 0.9,0.8, body extent -0.9,-0.8 0.9,0.8, height 0.56
ESD_SOT23-6L [mm]
  rect 0.6x1.2 smd mask+0.05: 1(-0.95,-1.15) 2(0,-1.15) 3(0.95,-1.15) 4(0.95,1.15) 5(0,1.15) 6(-0.95,1.15)
  silkscreen extent -1.53,-0.87 1.53,0.87, body extent -1.52,-1.5 1.52,1.5, height 1.45
ESD_SOT323-5L [mm]
  rect 0.4x1.2 smd mask+0.05: 1(-0.65,-0.85) 2(0,-0.85) 3(0.65,-0.85) 4(0.65,0.85) 5(-0.65,0.85)
  silkscreen extent -1.22,-1.21 1.22,0.77, body extent -1.15,-1.05 1.15,1.05, height 1.1
ESD_ST0201 [mm]
  rect 0.425x0.33 smd mask+0.05: 1(-0.312,0) 2(0.312,0)
  silkscreen extent -0.55,-0.3 0.33,0.3, body extent -0.34,-0.18 0.34,0.18, height 0.34
ESD_UQFN8-EPAD_1P7X1P5_P040 [mm]
  rect 0.2x0.6 smd mask+0.05: 1(-0.6,-0.75) 2(-0.2,-0.75) 3(0.2,-0.75) 4(0.6,-0.75) 5(0.6,0.75) 6(0.2,0.75) 7(-0.2,0.75) 8(-0.6,0.75)
  rect 1x0.4 smd mask+0.05: 9(0,0)
  silkscreen extent -1.07,-1.12 0.85,0.75, body extent -0.85,-0.75 0.85,0.75, height 0.61
ESD_UQFN-10L_2P5X1_P050 [mm]
  rect 0.2x0.58 smd mask+0.05: 1(-1,-0.41) 2(-0.5,-0.41) 4(0.5,-0.41) 5(1,-0.41) 6(1,0.41) 7(0.5,0.41) 9(-0.5,0.41) 10(-1,0.41)
  rect 0.4x0.58 smd mask+0.05: 3(0,-0.41) 8(0,0.41)
  silkscreen extent -1.38,-0.63 1.38,0.63, body extent -1.3,-0.55 1.3,0.55, height 0.51
ICC_BGA24_5X5-BALL-ARRAY_6X8_P1 [mm]
  round 0.45 smd mask+0.05: A2(-1,2) A3(0,2) A4(1,2) A5(2,2) B1(-2,1) B2(-1,1) B3(0,1) B4(1,1) B5(2,1) C1(-2,0) C2(-1,0) C3(0,0) C4(1,0) C5(2,0) D1(-2,-1) D2(-1,-1) D3(0,-1) D4(1,-1) D5(2,-1) E1(-2,-2) E2(-1,-2) E3(0,-2) E4(1,-2) E5(2,-2)
  silkscreen extent -3.05,-4.05 3.05,4.05, body extent -3.05,-4.05 3.05,4.05, height 1.2
ICC_DFN6-EPAD_3X3_P095 [mm]
  rect 0.45x0.5 smd mask+0.05: 1(-0.95,-1.3) 2(0,-1.3) 3(0.95,-1.3) 4(0.95,1.3) 5(0,1.3) 6(-0.95,1.3)
  rect 2.5x1.7 smd mask+0.05: EP(0,0)
  silkscreen extent -1.55,-1.55 1.55,1.55, body extent -1.55,-1.55 1.55,1.55, height 1
ICC_DFN12-EPAD_3X3_P045 [mm] "MCD-01952"
  rect 0.25x0.95 smd mask+0.05: 1(-1.125,-1.425) 2(-0.675,-1.425) 3(-0.225,-1.425) 4(0.225,-1.425) 5(0.675,-1.425) 6(1.125,-1.425) 7(1.125,1.425) 8(0.675,1.425) 9(0.225,1.425) 10(-0.225,1.425) 11(-0.675,1.425) 12(-1.125,1.425)
  rect 2.2x1.4 smd mask+0.05: 13(0,0)
  silkscreen extent -1.68,-1.97 1.55,1.55, body extent -1.55,-1.55 1.55,1.55, height 0.8
ICC_LGA14_3X2P5_P050 [mm] "MCD-01387"
  rect 0.8x0.3 smd mask+0.05: 1(-1.25,0.75) 2(-1.25,0.25) 3(-1.25,-0.25) 4(-1.25,-0.75) 8(1.25,-0.75) 9(1.25,-0.25) 10(1.25,0.25) 11(1.25,0.75)
  rect 0.3x0.8 smd mask+0.05: 5(-0.5,-1) 6(0,-1) 7(0.5,-1) 12(0.5,1) 13(0,1) 14(-0.5,1)
  silkscreen extent -1.75,-1.3 1.55,1.45, body extent -1.55,-1.3 1.55,1.3, height 0.86
ICC_LQFP48_7X7_P050 [mm]
  rect 0.3x1.2 smd mask+0.05: 1(-2.75,-4.25) 2(-2.25,-4.25) 3(-1.75,-4.25) 4(-1.25,-4.25) 5(-0.75,-4.25) 6(-0.25,-4.25) 7(0.25,-4.25) 8(0.75,-4.25) 9(1.25,-4.25) 10(1.75,-4.25) 11(2.25,-4.25) 12(2.75,-4.25) 25(2.75,4.25) 26(2.25,4.25) 27(1.75,4.25) 28(1.25,4.25) 29(0.75,4.25) 30(0.25,4.25) 31(-0.25,4.25) 32(-0.75,4.25) 33(-1.25,4.25) 34(-1.75,4.25) 35(-2.25,4.25) 36(-2.75,4.25)
  rect 1.2x0.3 smd mask+0.05: 13(4.25,-2.75) 14(4.25,-2.25) 15(4.25,-1.75) 16(4.25,-1.25) 17(4.25,-0.75) 18(4.25,-0.25) 19(4.25,0.25) 20(4.25,0.75) 21(4.25,1.25) 22(4.25,1.75) 23(4.25,2.25) 24(4.25,2.75) 37(-4.25,2.75) 38(-4.25,2.25) 39(-4.25,1.75) 40(-4.25,1.25) 41(-4.25,0.75) 42(-4.25,0.25) 43(-4.25,-0.25) 44(-4.25,-0.75) 45(-4.25,-1.25) 46(-4.25,-1.75) 47(-4.25,-2.25) 48(-4.25,-2.75)
  silkscreen extent -3.52,-3.52 3.52,3.52, body extent -4.5,-4.5 4.5,4.5, height 1.6
ICC_MINI-BGA48_9X11_P075 [mm] "IPC"
  round 0.28 smd mask+0.05: A1(-1.875,2.625) A2(-1.125,2.625) A3(-0.375,2.625) A4(0.375,2.625) A5(1.125,2.625) A6(1.875,2.625) B1(-1.875,1.875) B2(-1.125,1.875) B3(-0.375,1.875) B4(0.375,1.875) B5(1.125,1.875) B6(1.875,1.875) C1(-1.875,1.125) C2(-1.125,1.125) C3(-0.375,1.125) C4(0.375,1.125) C5(1.125,1.125) C6(1.875,1.125) D1(-1.875,0.375) D2(-1.125,0.375) D3(-0.375,0.375) D4(0.375,0.375) D5(1.125,0.375) D6(1.875,0.375) E1(-1.875,-0.375) E2(-1.125,-0.375) E3(-0.375,-0.375) E4(0.375,-0.375) E5(1.125,-0.375) E6(1.875,-0.375) F1(-1.875,-1.125) F2(-1.125,-1.125) F3(-0.375,-1.125) F4(0.375,-1.125) F5(1.125,-1.125) F6(1.875,-1.125) G1(-1.875,-1.875) G2(-1.125,-1.875) G3(-0.375,-1.875) G4(0.375,-1.875) G5(1.125,-1.875) G6(1.875,-1.875) H1(-1.875,-2.625) H2(-1.125,-2.625) H3(-0.375,-2.625) H4(0.375,-2.625) H5(1.125,-2.625) H6(1.875,-2.625)
  silkscreen extent -4.7,-5.55 4.55,5.7, body extent -4.55,-5.55 4.55,5.55, height 1.21
ICC_QFN12L-EPAD_3X3_P050 [mm] "MCD-01809"
  rect 0.3x0.75 smd mask+0.05: 1(-0.5,-1.425) 2(0,-1.425) 3(0.5,-1.425) 7(0.5,1.425) 8(0,1.425) 9(-0.5,1.425)
  rect 0.75x0.3 smd mask+0.05: 4(1.425,-0.5) 5(1.425,0) 6(1.425,0.5) 10(-1.425,0.5) 11(-1.425,0) 12(-1.425,-0.5)
  rect 1.7x1.7 smd mask+0.05: 13(0,0)
  silkscreen extent -1.55,-1.55 1.55,1.55, body extent -1.55,-1.55 1.55,1.55, height 0.8
ICC_QFN16-EPAD_4X4_P065 [mm]
  rect 0.35x0.7 smd mask+0.05: 1(-0.975,-1.9) 2(-0.325,-1.9) 3(0.325,-1.9) 4(0.975,-1.9) 9(0.975,1.9) 10(0.325,1.9) 11(-0.325,1.9) 12(-0.975,1.9)
  rect 0.7x0.35 smd mask+0.05: 5(1.9,-0.975) 6(1.9,-0.325) 7(1.9,0.325) 8(1.9,0.975) 13(-1.9,0.975) 14(-1.9,0.325) 15(-1.9,-0.325) 16(-1.9,-0.975)
  rect 2.7x2.7 smd mask+0.05: 17(0,0)
  silkscreen extent -2.05,-2.05 2.05,2.05, body extent -2.09,-2.08 2.08,2.09, height 1
ICC_QFN20-EPAD_4X4_P050 [mm] "MCD-02130"
  rect 0.75x0.3 smd mask+0.05: 1(-1.925,1) 2(-1.925,0.5) 3(-1.925,0) 4(-1.925,-0.5) 5(-1.925,-1) 11(1.925,-1) 12(1.925,-0.5) 13(1.925,0) 14(1.925,0.5) 15(1.925,1)
  rect 0.3x0.75 smd mask+0.05: 6(-1,-1.925) 7(-0.5,-1.925) 8(0,-1.925) 9(0.5,-1.925) 10(1,-1.925) 16(1,1.925) 17(0.5,1.925) 18(0,1.925) 19(-0.5,1.925) 20(-1,1.925)
  rect 2.7x2.7 smd mask+0.05: 21(0,0)
  silkscreen extent -2.07,-2.07 2.07,2.07, body extent -2.13,-2.13 2.13,2.13, height 1.01
ICC_QFN32-EPAD_5X5_P050 [mm]
  oval 0.3x0.75 smd mask+0.05: 1(-1.75,-2.425) 2(-1.25,-2.425) 3(-0.75,-2.425) 4(-0.25,-2.425) 5(0.25,-2.425) 6(0.75,-2.425) 7(1.25,-2.425) 8(1.75,-2.425) 17(1.75,2.425) 18(1.25,2.425) 19(0.75,2.425) 20(0.25,2.425) 21(-0.25,2.425) 22(-0.75,2.425) 23(-1.25,2.425) 24(-1.75,2.425)
  oval 0.75x0.3 smd mask+0.05: 9(2.425,-1.75) 10(2.425,-1.25) 11(2.425,-0.75) 12(2.425,-0.25) 13(2.425,0.25) 14(2.425,0.75) 15(2.425,1.25) 16(2.425,1.75) 25(-2.425,1.75) 26(-2.425,1.25) 27(-2.425,0.75) 28(-2.425,0.25) 29(-2.425,-0.25) 30(-2.425,-0.75) 31(-2.425,-1.25) 32(-2.425,-1.75)
  rect 3.7x3.7 smd mask+0.05: 33(0,0)
  silkscreen extent -2.63,-2.63 2.63,2.63, body extent -2.55,-2.55 2.55,2.55, height 1
ICC_SO8_5X4_P127 [mm]
  rect 0.7x1.75 smd mask+0.05: 1(-1.905,-2.375) 2(-0.635,-2.375) 3(0.635,-2.375) 4(1.905,-2.375) 5(1.905,2.375) 6(0.635,2.375) 7(-0.635,2.375) 8(-1.905,2.375)
  silkscreen extent -2.73,-3.25 2.58,2, body extent -2.57,-3 2.57,3, height 1.75
ICC_SO28_18P10X7P60_P127 [mm]
  rect 0.8x2.02 smd mask+0.05: 1(-8.255,-4.59) 2(-6.985,-4.59) 3(-5.715,-4.59) 4(-4.445,-4.59) 5(-3.175,-4.59) 6(-1.905,-4.59) 7(-0.635,-4.59) 8(0.635,-4.59) 9(1.905,-4.59) 10(3.175,-4.59) 11(4.445,-4.59) 12(5.715,-4.59) 13(6.985,-4.59) 14(8.255,-4.59) 15(8.255,4.59) 16(6.985,4.59) 17(5.715,4.59) 18(4.445,4.59) 19(3.175,4.59) 20(1.905,4.59) 21(0.635,4.59) 22(-0.635,4.59) 23(-1.905,4.59) 24(-3.175,4.59) 25(-4.445,4.59) 26(-5.715,4.59) 27(-6.985,4.59) 28(-8.255,4.59)
  silkscreen extent -9.05,-3.8 9.05,3.8, body extent -9.05,-5.16 9.05,5.16, height 2.65
ICC_SSOP28_10P2X5P3_P065 [mm]
  rect 0.45x1.9 smd mask+0.05: 1(-4.225,-3.45) 2(-3.575,-3.45) 3(-2.925,-3.45) 4(-2.275,-3.45) 5(-1.625,-3.45) 6(-0.975,-3.45) 7(-0.325,-3.45) 8(0.325,-3.45) 9(0.975,-3.45) 10(1.625,-3.45) 11(2.275,-3.45) 12(2.925,-3.45) 13(3.575,-3.45) 14(4.225,-3.45) 15(4.225,3.45) 16(3.575,3.45) 17(2.925,3.45) 18(2.275,3.45) 19(1.625,3.45) 20(0.975,3.45) 21(0.325,3.45) 22(-0.325,3.45) 23(-0.975,3.45) 24(-1.625,3.45) 25(-2.275,3.45) 26(-2.925,3.45) 27(-3.575,3.45) 28(-4.225,3.45)
  silkscreen extent -5.25,-2.8 5.25,2.8, body extent -5.25,-3.9 5.25,3.9, height 2
ICC_UFBGA169_7X7_P050_PAD025-PM030-SM035_SOCKET_IRONWOOD_CS1627113MF_NM [mm] "MCD-01902"
  round 0 hole 1.7 unplated mask+0.05: 0(-6.612,-6.362) 0(-6.612,6.363) 0(6.113,6.363) 0(6.113,-6.362)
  round 0 hole 0.85 unplated mask+0.05: 0(-6.612,-1.282) 0(6.113,3.823)
  round 0.25 smd paste+0.025 mask+0.05: A1(-3,3) A2(-2.5,3) A3(-2,3) A4(-1.5,3) A5(-1,3) A6(-0.5,3) A7(0,3) A8(0.5,3) A9(1,3) A10(1.5,3) A11(2,3) A12(2.5,3) A13(3,3) B1(-3,2.5) B2(-2.5,2.5) B3(-2,2.5) B4(-1.5,2.5) B5(-1,2.5) B6(-0.5,2.5) B7(0,2.5) B8(0.5,2.5) B9(1,2.5) B10(1.5,2.5) B11(2,2.5) B12(2.5,2.5) B13(3,2.5) C1(-3,2) C2(-2.5,2) C3(-2,2) C4(-1.5,2) C5(-1,2) C6(-0.5,2) C7(0,2) C8(0.5,2) C9(1,2) C10(1.5,2) C11(2,2) C12(2.5,2) C13(3,2) D1(-3,1.5) D2(-2.5,1.5) D3(-2,1.5) D4(-1.5,1.5) D5(-1,1.5) D6(-0.5,1.5) D7(0,1.5) D8(0.5,1.5) D9(1,1.5) D10(1.5,1.5) D11(2,1.5) D12(2.5,1.5) D13(3,1.5) E1(-3,1) E2(-2.5,1) E3(-2,1) E4(-1.5,1) E5(-1,1) E6(-0.5,1) E7(0,1) E8(0.5,1) E9(1,1) E10(1.5,1) E11(2,1) E12(2.5,1) E13(3,1) F1(-3,0.5) F2(-2.5,0.5) F3(-2,0.5) F4(-1.5,0.5) F5(-1,0.5) F6(-0.5,0.5) F7(0,0.5) F8(0.5,0.5) F9(1,0.5) F10(1.5,0.5) F11(2,0.5) F12(2.5,0.5) F13(3,0.5) G1(-3,0) G2(-2.5,0) G3(-2,0) G4(-1.5,0) G5(-1,0) G6(-0.5,0) G7(0,0) G8(0.5,0) G9(1,0) G10(1.5,0) G11(2,0) G12(2.5,0) G13(3,0) H1(-3,-0.5) H2(-2.5,-0.5) H3(-2,-0.5) H4(-1.5,-0.5) H5(-1,-0.5) H6(-0.5,-0.5) H7(0,-0.5) H8(0.5,-0.5) H9(1,-0.5) H10(1.5,-0.5) H11(2,-0.5) H12(2.5,-0.5) H13(3,-0.5) J1(-3,-1) J2(-2.5,-1) J3(-2,-1) J4(-1.5,-1) J5(-1,-1) J6(-0.5,-1) J7(0,-1) J8(0.5,-1) J9(1,-1) J10(1.5,-1) J11(2,-1) J12(2.5,-1) J13(3,-1) K1(-3,-1.5) K2(-2.5,-1.5) K3(-2,-1.5) K4(-1.5,-1.5) K5(-1,-1.5) K6(-0.5,-1.5) K7(0,-1.5) K8(0.5,-1.5) K9(1,-1.5) K10(1.5,-1.5) K11(2,-1.5) K12(2.5,-1.5) K13(3,-1.5) L1(-3,-2) L2(-2.5,-2) L3(-2,-2) L4(-1.5,-2) L5(-1,-2) L6(-0.5,-2) L7(0,-2) L8(0.5,-2) L9(1,-2) L10(1.5,-2) L11(2,-2) L12(2.5,-2) L13(3,-2) M1(-3,-2.5) M2(-2.5,-2.5) M3(-2,-2.5) M4(-1.5,-2.5) M5(-1,-2.5) M6(-0.5,-2.5) M7(0,-2.5) M8(0.5,-2.5) M9(1,-2.5) M10(1.5,-2.5) M11(2,-2.5) M12(2.5,-2.5) M13(3,-2.5) N1(-3,-3) N2(-2.5,-3) N3(-2,-3) N4(-1.5,-3) N5(-1,-3) N6(-0.5,-3) N7(0,-3) N8(0.5,-3) N9(1,-3) N10(1.5,-3) N11(2,-3) N12(2.5,-3) N13(3,-3)
  Bottom Layer keep-out circle w0.01: c-6.612,-6.362 r2.2
  Bottom Layer keep-out circle w0.01: c6.113,-6.362 r2.2
  Bottom Layer keep-out circle w0.01: c6.113,6.363 r2.2
  Bottom Layer keep-out circle w0.01: c-0.25,0 r2.2
  Bottom Layer keep-out circle w0.01: c-6.612,6.363 r2.2
  silkscreen extent -8,-7.61 7.36,7.75, body extent -3.5,-3.5 3.5,3.5, height 0.61
ICC_UFBGA201_176+25_10X10_P065 [mm] "IPC"
  round 0.25 smd mask+0.05: A1(-4.55,4.55) A2(-3.9,4.55) A3(-3.25,4.55) A4(-2.6,4.55) A5(-1.95,4.55) A6(-1.3,4.55) A7(-0.65,4.55) A8(0,4.55) A9(0.65,4.55) A10(1.3,4.55) A11(1.95,4.55) A12(2.6,4.55) A13(3.25,4.55) A14(3.9,4.55) A15(4.55,4.55) B1(-4.55,3.9) B2(-3.9,3.9) B3(-3.25,3.9) B4(-2.6,3.9) B5(-1.95,3.9) B6(-1.3,3.9) B7(-0.65,3.9) B8(0,3.9) B9(0.65,3.9) B10(1.3,3.9) B11(1.95,3.9) B12(2.6,3.9) B13(3.25,3.9) B14(3.9,3.9) B15(4.55,3.9) C1(-4.55,3.25) C2(-3.9,3.25) C3(-3.25,3.25) C4(-2.6,3.25) C5(-1.95,3.25) C6(-1.3,3.25) C7(-0.65,3.25) C8(0,3.25) C9(0.65,3.25) C10(1.3,3.25) C11(1.95,3.25) C12(2.6,3.25) C13(3.25,3.25) C14(3.9,3.25) C15(4.55,3.25) D1(-4.55,2.6) D2(-3.9,2.6) D3(-3.25,2.6) D4(-2.6,2.6) D5(-1.95,2.6) D6(-1.3,2.6) D7(-0.65,2.6) D8(0,2.6) D9(0.65,2.6) D10(1.3,2.6) D11(1.95,2.6) D12(2.6,2.6) D13(3.25,2.6) D14(3.9,2.6) D15(4.55,2.6) E1(-4.55,1.95) E2(-3.9,1.95) E3(-3.25,1.95) E4(-2.6,1.95) E12(2.6,1.95) E13(3.25,1.95) E14(3.9,1.95) E15(4.55,1.95) F1(-4.55,1.3) F2(-3.9,1.3) F3(-3.25,1.3) F4(-2.6,1.3) F6(-1.3,1.3) F7(-0.65,1.3) F8(0,1.3) F9(0.65,1.3) F10(1.3,1.3) F12(2.6,1.3) F13(3.25,1.3) F14(3.9,1.3) F15(4.55,1.3) G1(-4.55,0.65) G2(-3.9,0.65) G3(-3.25,0.65) G4(-2.6,0.65) G6(-1.3,0.65) G7(-0.65,0.65) G8(0,0.65) G9(0.65,0.65) G10(1.3,0.65) G12(2.6,0.65) G13(3.25,0.65) G14(3.9,0.65) G15(4.55,0.65) H1(-4.55,0) H2(-3.9,0) H3(-3.25,0) H4(-2.6,0) H6(-1.3,0) H7(-0.65,0) H8(0,0) H9(0.65,0) H10(1.3,0) H12(2.6,0) H13(3.25,0) H14(3.9,0) H15(4.55,0) J1(-4.55,-0.65) J2(-3.9,-0.65) J3(-3.25,-0.65) J4(-2.6,-0.65) J6(-1.3,-0.65) J7(-0.65,-0.65) J8(0,-0.65) J9(0.65,-0.65) J10(1.3,-0.65) J12(2.6,-0.65) J13(3.25,-0.65) J14(3.9,-0.65) J15(4.55,-0.65) K1(-4.55,-1.3) K2(-3.9,-1.3) K3(-3.25,-1.3) K4(-2.6,-1.3) K6(-1.3,-1.3) K7(-0.65,-1.3) K8(0,-1.3) K9(0.65,-1.3) K10(1.3,-1.3) K12(2.6,-1.3) K13(3.25,-1.3) K14(3.9,-1.3) K15(4.55,-1.3) L1(-4.55,-1.95) L2(-3.9,-1.95) L3(-3.25,-1.95) L4(-2.6,-1.95) L12(2.6,-1.95) L13(3.25,-1.95) L14(3.9,-1.95) L15(4.55,-1.95) M1(-4.55,-2.6) M2(-3.9,-2.6) M3(-3.25,-2.6) M4(-2.6,-2.6) M5(-1.95,-2.6) M6(-1.3,-2.6) M7(-0.65,-2.6) M8(0,-2.6) M9(0.65,-2.6) M10(1.3,-2.6) M11(1.95,-2.6) M12(2.6,-2.6) M13(3.25,-2.6) M14(3.9,-2.6) M15(4.55,-2.6) N1(-4.55,-3.25) N2(-3.9,-3.25) N3(-3.25,-3.25) N4(-2.6,-3.25) N5(-1.95,-3.25) N6(-1.3,-3.25) N7(-0.65,-3.25) N8(0,-3.25) N9(0.65,-3.25) N10(1.3,-3.25) N11(1.95,-3.25) N12(2.6,-3.25) N13(3.25,-3.25) N14(3.9,-3.25) N15(4.55,-3.25) P1(-4.55,-3.9) P2(-3.9,-3.9) P3(-3.25,-3.9) P4(-2.6,-3.9) P5(-1.95,-3.9) P6(-1.3,-3.9) P7(-0.65,-3.9) P8(0,-3.9) P9(0.65,-3.9) P10(1.3,-3.9) P11(1.95,-3.9) P12(2.6,-3.9) P13(3.25,-3.9) P14(3.9,-3.9) P15(4.55,-3.9) R1(-4.55,-4.55) R2(-3.9,-4.55) R3(-3.25,-4.55) R4(-2.6,-4.55) R5(-1.95,-4.55) R6(-1.3,-4.55) R7(-0.65,-4.55) R8(0,-4.55) R9(0.65,-4.55) R10(1.3,-4.55) R11(1.95,-4.55) R12(2.6,-4.55) R13(3.25,-4.55) R14(3.9,-4.55) R15(4.55,-4.55)
  silkscreen extent -5.22,-5.07 5.07,5.23, body extent -5.07,-5.07 5.07,5.07, height 0.61
ICC_UFQFN16-EPAD_2P6X1P8_P040 [mm]
  rect 0.2x0.35 smd mask+0.05: 1(-0.6,-0.775) 2(-0.2,-0.775) 3(0.2,-0.775) 4(0.6,-0.775) 9(0.6,0.775) 10(0.2,0.775) 11(-0.2,0.775) 12(-0.6,0.775)
  rect 0.35x0.2 smd mask+0.05: 5(1.175,-0.6) 6(1.175,-0.2) 7(1.175,0.2) 8(1.175,0.6) 13(-1.175,0.6) 14(-1.175,0.2) 15(-1.175,-0.2) 16(-1.175,-0.6)
  rect 1.6x0.8 smd mask+0.05: 17(0,0)
  silkscreen extent -1.33,-0.92 1.33,0.92, body extent -1.33,-0.92 1.33,0.92, height 0.56
ICC_VSSOP8_DCU_R-PDSO-G8_2X2P30_P050 [mm]
  rect 0.3x0.8 smd mask+0.05: 1(-0.75,-1.55) 2(-0.25,-1.55) 3(0.25,-1.55) 4(0.75,-1.55) 5(0.75,1.55) 6(0.25,1.55) 7(-0.25,1.55) 8(-0.75,1.55)
  silkscreen extent -1.05,-1.2 1.05,1.2, body extent -1.05,-1.62 1.05,1.62, height 0.9
ICC_WSON8-EPAD_2X2_P050 [mm] "MCD-02194"
  rect 0.5x0.3 smd paste+0 mask+0.05: 1(-0.9,0.75) 2(-0.9,0.25) 3(-0.9,-0.25) 4(-0.9,-0.75) 5(0.9,-0.75) 6(0.9,-0.25) 7(0.9,0.25) 8(0.9,0.75)
  rect 0.9x1.6 smd paste+0 mask+0.05: 9(0,0)
  silkscreen extent -0.5,-1 0.5,1, body extent -1,-1 1,1, height 0.81
L0603 [mm]
  rect 0.8x0.95 smd mask+0.05: 1(-0.8,0) 2(0.8,0)
  silkscreen extent -1.33,-0.6 1.33,0.6, body extent -0.87,-0.47 0.87,0.47, height 0.95
L0805_H0P9 [mm]
  rect 1.1x1.6 smd mask+0.05: 1(-0.75,0) 2(0.75,0)
  silkscreen extent -0.08,-0.7 0.08,0.7, body extent -1.07,-0.7 1.07,0.7, height 1.2
LED_0603_OSRAM_LG-Q396-PS-35_GREEN_1A2K_H0P4 [mm]
  rect 0.8x0.8 smd mask+0.05: 1(-0.75,0) 2(0.75,0)
  silkscreen extent -0.85,-0.53 1.28,0.53, body extent -0.85,-0.45 0.85,0.45, height 0.6
LED_0603_OSRAM_LY-Q396-P1Q2-36_YELLOW_1A2K_H0P4 [mm]
  rect 0.8x0.8 smd mask+0.05: 1(-0.75,0) 2(0.75,0)
  silkscreen extent -0.85,-0.53 1.28,0.53, body extent -0.85,-0.45 0.85,0.45, height 0.4
LED_0603_SMD-B_BLUE_H0P4 [mm]
  rect 0.6x1 smd mask+0.05: 1(-0.65,0) 2(0.65,0)
  silkscreen extent -0.23,-0.45 1.07,0.45, body extent -0.85,-0.45 0.85,0.45, height 0.5
LED_0603_VISHAY_VLMS1300-GS08_RED_1A2K_H0P8 [mm]
  rect 0.8x0.8 smd mask+0.05: 1(-0.75,0) 2(0.75,0)
  silkscreen extent -0.85,-0.53 1.28,0.53, body extent -0.85,-0.45 0.85,0.45, height 0.8
LED_BI-GR_HSMF-A201-A00J1 [mm] "MCD-00051"
  rect 1.1x1.5 smd mask+0.05: 1(-0.75,-1.5) 2(-0.75,1.5) 3(0.75,1.5) 4(0.75,-1.5)
  silkscreen extent -1.65,-1.85 1.5,1.7, body extent -1.5,-1.85 1.5,1.85, height 2.1
MIC_STM_MP23DB01MMTR [mm]
  rect 0.725x0.522 smd mask+0.05: 1(-0.838,1.364) 2(-0.838,0.542) 4(0.838,0.542) 5(0.838,1.364)
  round 0.2 smd mask+0.05: 3(0,-1.373)
  round 0 hole 0.325 unplated mask+0.05: 6(0,-0.71)
  Top Layer circle w0.3: c0,-0.71 r0.663
  silkscreen extent -1.33,-1.75 1.33,1.75, body extent -1.33,-1.76 1.33,1.75, height 1.09
MIRE_PLACE_SMD_0P8MM [mm]
  round 0.8 smd paste-10 mask+0.2: 1(0,0)
  Top Layer keep-out circle w0.01: c0,0 r0.804
MOS_POWERFLAT_3P3X3P3_P065 [mm] "MCD-01126"
  rect 0.4x0.75 smd mask+0.05: 1(-0.975,-1.525) 2(-0.325,-1.525) 3(0.325,-1.525) 4(0.975,-1.525) 6(0.325,1.525) 7(-0.325,1.525)
  rect 0.45x0.75 smd mask+0.05: 5(1,1.525) 8(-1,1.525)
  Top Layer region: -1.755,0.2 -1.755,-0.2 -1.225,-0.2 -1.225,-0.5 1.225,-0.5 1.225,-0.2 1.755,-0.2 1.755,0.2 1.225,0.2 1.225,1.9 -1.225,1.9 -1.225,0.2
  silkscreen extent -1.63,-1.55 1.63,1.55, body extent -1.75,-1.75 1.75,1.75, height 0.91
MOS_SOT23 [mm]
  rect 1x1.4 smd mask+0.05: 1(-0.95,-1.1) 2(0.95,-1.1) 3(0,1.1)
  silkscreen extent -1.63,-0.82 1.63,0.82, body extent -1.56,-1.25 1.56,1.25, height 1.1
MOS_SOT23-5L [mm]
  rect 0.6x1.3 smd mask+0.05: 1(-0.95,-1.1) 2(0,-1.1) 3(0.95,-1.1) 4(0.95,1.1) 5(-0.95,1.1)
  silkscreen extent -1.6,-0.95 1.6,0.97, body extent -1.52,-1.25 1.52,1.25, height 1.45
NPN_SOT23 [mm]
  rect 1x1.4 smd mask+0.05: 1(-0.95,-1.1) 2(0.95,-1.1) 3(0,1.1)
  silkscreen extent -1.63,-0.82 1.63,0.82, body extent -1.56,-1.25 1.56,1.25, height 1.1
OSC_NDK_NZ2520SB_4P [mm]
  rect 1x1 smd mask+0.05: 1(-0.825,-0.625) 2(0.825,-0.625) 3(0.825,0.625) 4(-0.825,0.625)
  silkscreen extent -1.43,-1.22 1.2,1.05, body extent -1.3,-1.05 1.3,1.05, height 0.91
PHO_SENBAN_GL55XX [mm]
  round 1.5 hole 0.9 mask+0.05: 1(-1.7,0) 2(1.7,0)
  silkscreen extent -2.6,-2.25 2.6,2.25, body extent -2.6,-2.25 2.6,2.25, height 5.21
POT_BOURNS_3314J-1 [mm]
  rect 1.3x2 smd mask+0.05: 1(1.15,-2) 3(-1.15,-2)
  rect 2x2 smd mask+0.05: 2(0,2)
  silkscreen extent -2.5,-3 2.5,2.25, body extent -2.5,-2.5 2.5,2.5, height 2.73
POT_BOURNS_3386P [mm]
  rect 1.7x1.7 hole 0.8 mask+0.05: 1(-2.54,0.02)
  round 1.7 hole 0.8 mask+0.05: 2(0,-2.52) 3(2.54,0.02)
  silkscreen extent -4.8,-4.8 4.8,4.8, body extent -4.8,-4.8 4.8,4.81, height 4.96
POT_BOURNS_3386P-1-101TLF [mm] "MCD-02026"
  rect 1.7x1.7 hole 0.8 mask+0.05: 1(-2.54,0.02)
  round 1.7 hole 0.8 mask+0.05: 2(0,-2.52) 3(2.54,0.02)
  silkscreen extent -4.8,-4.8 4.8,4.8, body extent -4.8,-4.8 4.8,5.04, height 10.42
